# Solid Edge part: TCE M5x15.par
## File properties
Title: 4320011799
Subject: Vite TCEI M5x15 brunita
Author: b_giovanelli
Template: RBuno.par
Last saved by: g_deluca
Revision: 25
Application: Solid Edge
Company: EFFEBI S.p.A.
Codice: Codice
Indice rev.: Rev.
Data rev.: Data rev.
Firma rev.: Firma rev.
Descrizione rev.: Descrizione rev.
Densità: 7860.000 kg/m^3
Precisione: 0.99
Tipo di contenuto documento: 0
Document Number: UNI 5931
Material: Classe 8.8
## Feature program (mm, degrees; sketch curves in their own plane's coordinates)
sketch for "unnamed Protrusion 1" plane through (0, 0, 0) normal (0, 0, 1) x-axis (1, 0, 0)
extrude "unnamed Protrusion 1" add finite 5 along +normal
sketch for "ExtrudedCutout_1" plane through (0, 0, 5) normal (0, 0, 1) x-axis (-1, 0, 0)
  line (2, 1.1547) -> (2, -1.1547)
  line (0, -2.3094) -> (2, -1.1547)
  line (-2, -1.1547) -> (0, -2.3094)
  line (-2, 1.1547) -> (-2, -1.1547)
  line (-2, 1.1547) -> (0, 2.3094)
  line (0, 2.3094) -> (2, 1.1547)
extrude "ExtrudedCutout_1" cut finite 3 along -normal
sketch for "ExtrudedProtrusion_4" plane through (0, 0, 0) normal (0, 0, -1) x-axis (0, -1, 0)
extrude "ExtrudedProtrusion_4" add finite 15 along +normal
thread "Filettatura_3"  ThreadDepth = 15 mm
fillet "Rotondo_2" radius 0.5
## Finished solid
Body 1: solid body, 19 faces, 35 edges, 18 vertices.
  Faces by surface: plane 10, cylinder 8, torus 1
  Edges by curve: line 24, ellipse 6, circle 5
Bounding box of the edges (mm; curved faces can reach further): 8.500 x 8.500 x 20.000, from (-4.25, -4.25, -15) to (4.25, 4.25, 5).
Cylindrical faces by radius (mm): R0.5 x6, R2.5 x1, R4.25 x1
Toroidal faces (ring radius, tube radius in mm): R3.75 r0.5 x1
Planar faces by outward normal: +x 1, +z 2, -x 1, -z 2, oblique 4
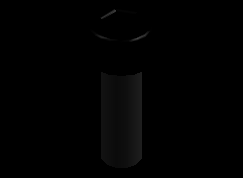
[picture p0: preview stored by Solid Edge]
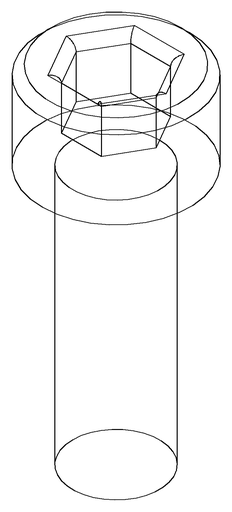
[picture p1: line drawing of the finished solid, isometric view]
